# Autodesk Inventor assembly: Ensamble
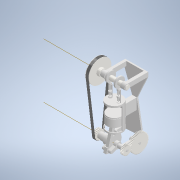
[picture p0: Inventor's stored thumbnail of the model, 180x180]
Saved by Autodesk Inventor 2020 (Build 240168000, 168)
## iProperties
Created: 2019-09
Part Number: Ensamble
Document SubType Name: Assembly
Designer: user
Author: user
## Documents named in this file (10)
- C:\Users\user\Documents\EIA\Cursos\Diseño asistido por computador\Parcial\2019-II\Archivos BancoDP Animado\Ensamble.iam
- C:\Users\user\Documents\EIA\Cursos\Diseño asistido por computador\Parcial\2019-II\Archivos BancoDP Animado\Bloque del motor.ipt
- C:\Users\user\Documents\EIA\Cursos\Diseño asistido por computador\Parcial\2019-II\Archivos BancoDP Animado\Cigueñal.ipt
- C:\Users\user\Documents\EIA\Cursos\Diseño asistido por computador\Parcial\2019-II\Archivos BancoDP Animado\Ensamble\Design Accelerator\Spur Gears1.iam
- C:\Users\user\Documents\EIA\Cursos\Diseño asistido por computador\Parcial\2019-II\Archivos BancoDP Animado\Ensamble\Design Accelerator\Synchronous Belts Transmission1.iam
- C:\Users\user\Documents\EIA\Cursos\Diseño asistido por computador\Parcial\2019-II\Archivos BancoDP Animado\Shaft1.ipt
- C:\Users\user\Documents\EIA\Cursos\Diseño asistido por computador\Parcial\2019-II\Archivos BancoDP Animado\Leva.ipt
- C:\Users\user\Documents\EIA\Cursos\Diseño asistido por computador\Parcial\2019-II\Archivos BancoDP Animado\Válvula.ipt
- C:\Users\user\Documents\EIA\Cursos\Diseño asistido por computador\Parcial\2019-II\Archivos BancoDP Animado\Biela.ipt
- C:\Users\user\Documents\EIA\Cursos\Diseño asistido por computador\Parcial\2019-II\Archivos BancoDP Animado\Pistón.ipt
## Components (11 placed, 9 different names)
1. Bloque del motor:1 — Insert:1, Mate:3, Mate:4, Mate:5, Flush:1, Mate:6, Mate:7, Mate:8, Flush:2
2. Cigueñal:1 — Insert:1, Mate:1, Mate:2, Angle:1, Angle:3, Insert:5
3. Spur Gears:1 [sub-assembly] — Mate:1, Mate:2, Mate:3, Mate:4, Angle:1
4. Synchronous Belts Transmission:1 [sub-assembly] — Angle:2, Angle:3, Insert:7
5. Shaft:1 — Angle:2, Insert:3, Insert:4, Angle:4, Angle:5, Insert:7
6. Leva:1 — Insert:4, Angle:5
7. Leva:2 — Insert:3, Angle:4
8. Válvula:1 — Mate:6, Mate:7
9. Válvula:2 — Mate:5, Flush:1
10. Biela:1 — Insert:5, Insert:6
11. Pistón:1 — Mate:8, Flush:2, Insert:6
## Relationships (21: Mate 8, Insert 6, Angle 5, Flush 2)
- Insert:1: Bloque del motor:1 ↔ Cigueñal:1
- Mate:1: Cigueñal:1 ↔ Spur Gears:1
- Mate:2: Cigueñal:1 ↔ Spur Gears:1
- Mate:3: Bloque del motor:1 ↔ Spur Gears:1
- Mate:4: Bloque del motor:1 ↔ Spur Gears:1
- Angle:1: Cigueñal:1 ↔ Spur Gears:1
- Angle:2: Synchronous Belts Transmission:1 ↔ Shaft:1
- Angle:3: Cigueñal:1 ↔ Synchronous Belts Transmission:1
- Insert:3: Shaft:1 ↔ Leva:2
- Insert:4: Shaft:1 ↔ Leva:1
- Mate:5: Bloque del motor:1 ↔ Válvula:2
- Flush:1: Bloque del motor:1 ↔ Válvula:2
- Mate:6: Bloque del motor:1 ↔ Válvula:1
- Mate:7: Bloque del motor:1 ↔ Válvula:1
- Insert:5: Cigueñal:1 ↔ Biela:1
- Mate:8: Bloque del motor:1 ↔ Pistón:1
- Flush:2: Bloque del motor:1 ↔ Pistón:1
- Insert:6: Biela:1 ↔ Pistón:1
- Angle:4: Shaft:1 ↔ Leva:2
- Angle:5: Shaft:1 ↔ Leva:1
- Insert:7: Synchronous Belts Transmission:1 ↔ Shaft:1
